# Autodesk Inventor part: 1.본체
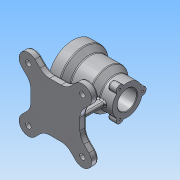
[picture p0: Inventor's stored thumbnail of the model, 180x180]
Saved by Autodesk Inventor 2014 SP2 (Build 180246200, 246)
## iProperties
Created: 2017-03
Part Number: 1.본체
Material: 알루미늄 6061
Document SubType Name: Modeling
Designer: SDA
Density: 2.71 g/cm^3
Appearance: 알루미늄 - 평지
Author: SDA
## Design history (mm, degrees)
sketch "스케치1"
  geometry: L1 (0, 0)-(100, 0); L2 (0, 0)-(0, 45); L3 (0, 45)-(20, 45); L4 (20, 45)-(31, 36); L5 (31, 36)-(65, 36); L6 (65, 36)-(77, 27.5); L7 (77, 27.5)-(100, 27.5); L8 (100, 27.5)-(100, 0)
  constraints: 16 end point, 4 horizontal, 2 vertical
  dimensions: "d0" = 100 distance of L1.start L1.end; "d1" = 90 diameter of L3 L1; "d2" = 72 diameter of L5 L1; "d3" = 55 diameter of L7 L1; "d4" = 20 distance of L2.end L3.end; "d5" = 31 distance from line of L4.end L2; "d6" = 65 distance from line of L2 L5.end; "d7" = 23 distance from line of L8 L6.end
revolve "회전1" sketch "스케치1" stored, may be unused: angle "d8" = 90 deg
sketch "스케치2"
  geometry: C1 r 35 at (0, 0); C2 r 45 at (0, 0) reference
  constraints: 1 centre point, 1 coincident
  dimensions: "d9" = 70 diameter of C1
extrude "돌출1" cut sketch "스케치2" distance "d10" = 23; taper "d11" = 0 deg
sketch "스케치4"
  geometry: C1 r 35 at (0, 0) reference; C2 r 26 at (0, 0)
  constraints: 1 centre point, 1 coincident
  dimensions: "d12" = 52 diameter of C2
extrude "돌출2" cut sketch "스케치4" distance "d13" = 47; taper "d14" = 0 deg
sketch "스케치5"
  geometry: C1 r 26 at (0, 0) reference; C2 r 17.5 at (0, 0)
  constraints: 1 centre point, 1 coincident
  dimensions: "d15" = 35 diameter of C2
extrude "돌출3" cut sketch "스케치5" distance "d16" = 30; taper "d17" = 0 deg
sketch "스케치6"
  geometry: C1 r 17.5 at (0, 0) reference; A1 r 7 centre (0, 27.5) between (6.943, 26.609) and (-6.943, 26.609); A2 r 27.5 centre (0, 0) between (-6.943, 26.609) and (6.943, 26.609) reference; A3 r 27.5 centre (0, 0) between (6.943, 26.609) and (-6.943, 26.609); A4 r 7 centre (-23.816, -13.75) between (-26.516, -7.292) and (-19.573, -19.317); A5 r 27.5 centre (0, 0) between (-26.516, -7.292) and (-19.573, -19.317); A6 r 7 centre (23.816, -13.75) between (19.573, -19.317) and (26.516, -7.292); A7 r 27.5 centre (0, 0) between (19.573, -19.317) and (26.516, -7.292); 1 further point
  constraints: 14 point on circle, 6 centre point, 1 coincident, 1 vertical alignment, 19 other
  dimensions: "d18" = 14 diameter of A1; "d19" = 27.5 distance of point (0, 0) A1.centre; "d23" = 360 deg dimension on A2.centre A1.centre (derived)
extrude "돌출4" join sketch "스케치6" distance "d25" = 15; taper "d26" = 0 deg
sketch "스케치7"
  geometry: A1 r 7 centre (0, 0) between (6.943, -0.891) and (-6.943, -0.891) reference; 1 further point
  constraints: 1 coincident
hole "구멍1" sketch "스케치7" at (0, 0) diameter "d27" = 3.459; stored, may be unused: countersink angle "d31" = 90 deg, drill point angle "d33" = 118 deg; dims "d28" = 9, "d29" = 4, "d30" = 2, "d32" = 11
sketch "스케치8"
  geometry: C1 r 35 at (0, 0) reference; 1 further point
  constraints: 1 vertical alignment
  dimensions: "d38" = 40 distance of C1.centre point (0, 40)
hole "구멍2" sketch "스케치8" at (0, 40) diameter "d39" = 3.459; stored, may be unused: countersink angle "d43" = 90 deg, drill point angle "d45" = 118 deg; dims "d40" = 9, "d41" = 4, "d42" = 2, "d44" = 11
node "작업 평면1"
sketch "스케치9"
  geometry: L1 (-11, 1.73)-(-12.039, 0) reference; L2 (-12.039, 0)-(-11, -1.73) reference; L3 (-11, -1.73)-(0, -1.73) reference; L4 (0, -1.73)-(0, -20.616) reference; L5 (0, -20.616)-(-20, -20.616) reference; L6 (-20, 20.616)-(0, 20.616) reference; L7 (0, 20.616)-(0, 1.73) reference; L8 (0, 1.73)-(-11, 1.73) reference; L9 (-31, 36)-(-65, 36) reference; L10 (-31, -36)-(-65, -36) reference; L11 (-100, 27.5)-(-100, 6.943) reference; C1 r 5 at (-50, 0); 2 further points
  constraints: 1 centre point, 1 vertical alignment
  dimensions: "d50" = 10 diameter of C1; "d51" = 36 distance from line of L9 C1.centre; "d52" = 50 distance from line of C1.centre L11
extrude "돌출5" join sketch "스케치9" stored distance "d53" = 15; taper "d54" = 0 deg
hole "구멍3" diameter "d57" = 4.459; stored, may be unused: countersink angle "d61" = 90 deg, drill point angle "d63" = 118 deg; dims "d58" = 14, "d59" = 4, "d60" = 2, "d62" = 14, "d174" = 10, "d175" = 10
node "작업 평면2"
sketch "스케치11"
  geometry: L1 (-10.072, 0)-(98.226, 0); L2 (11.518, 37.477)-(2.322, 28.281); L3 (-12.523, 61.518)-(-21.719, 52.322); L4 (-5, 0)-(-5, 10.603); L5 (-87.477, 61.518)-(-78.281, 52.322); L6 (-111.518, 37.477)-(-102.322, 28.281); L7 (-95, 0)-(-95, 10.603); L8 (-50, 45)-(-39.397, 45); L9 (-50, 45)-(-60.603, 45); L10 (11.518, -37.477)-(2.322, -28.281); L11 (-12.523, -61.518)-(-21.719, -52.322); L12 (-50, -45)-(-39.397, -45); L13 (-50, -45)-(-60.603, -45); L14 (-87.477, -61.518)-(-78.281, -52.322); L15 (-111.518, -37.477)-(-102.322, -28.281); L16 (-95, 0)-(-95, -10.603); L17 (-5, 0)-(-5, -10.603); C1 r 5 at (-50, 0) reference; C2 r 2.229 at (-50, 0) reference; A1 r 17 centre (-0.503, 49.497) between (11.518, 37.477) and (-13.894, 59.97); A2 r 25 centre (20, 10.603) between (2.322, 28.281) and (-5, 10.603); A3 r 17 centre (-99.497, 49.497) between (-87.477, 61.518) and (-111.518, 37.477); A4 r 25 centre (-120, 10.603) between (-95, 10.603) and (-102.322, 28.281); A5 r 25 centre (-39.397, 70) between (-39.397, 45) and (-21.719, 52.322); A6 r 25 centre (-60.603, 70) between (-78.281, 52.322) and (-60.603, 45); A7 r 25 centre (20, -10.603) between (-5, -10.603) and (2.322, -28.281); A8 r 17 centre (-0.503, -49.497) between (-12.523, -61.518) and (11.518, -37.477); A9 r 25 centre (-39.397, -70) between (-21.719, -52.322) and (-39.397, -45); A10 r 25 centre (-60.603, -70) between (-60.603, -45) and (-78.281, -52.322); A11 r 25 centre (-120, -10.603) between (-102.322, -28.281) and (-95, -10.603); A12 r 17 centre (-99.497, -49.497) between (-111.518, -37.477) and (-87.477, -61.518); 12 further points
  constraints: 34 end point, 25 point on circle, 12 centre point, 6 tangent, 2 horizontal, 1 parallel, 1 perpendicular, 1 vertical
extrude "돌출6" join sketch "스케치11" distance "d153" = 12; taper "d154" = 0 deg
sketch "스케치12"
  geometry: C1 r 5 at (0.503, 49.497); C2 r 5 at (99.497, 49.497); C3 r 5 at (99.497, -49.497); C4 r 5 at (0.503, -49.497); A1 r 17 centre (0.503, -49.497) between (-11.518, -37.477) and (12.523, -61.518) reference; A2 r 17 centre (99.497, -49.497) between (87.477, -61.518) and (111.518, -37.477) reference; A3 r 17 centre (99.497, 49.497) between (111.518, 37.477) and (87.477, 61.518) reference; A4 r 17 centre (0.503, 49.497) between (12.523, 61.518) and (-11.518, 37.477) reference; 1 further point
  constraints: 4 centre point, 4 coincident
  dimensions: "d155" = 10 diameter of C1; "d156" = 10 diameter of C2; "d157" = 10 diameter of C3; "d158" = 10 diameter of C4
extrude "돌출7" cut sketch "스케치12" distance "d159" = 12; taper "d160" = 0 deg
node "작업 평면3"
sketch "스케치13"
  geometry: L1 (45, -70)-(45, -82) reference; L2 (45, -82)-(-45, -82) reference; L3 (-45, -82)-(-45, -70) reference; L4 (-45, -70)-(45, -70) reference; L5 (5, 40)-(5, 35.651) reference; L6 (-5, 40)-(-2.229, 40) reference; L7 (-5, 35.651)-(-5, 40) reference; L8 (2.229, 40)-(5, 40) reference; L9 (37.477, -70)-(28.281, -70) reference; L10 (45, -70)-(52.322, -70) reference; L11 (0, -72)-(25, -72); L12 (25, -72)-(16.841, -25.731); L13 (16.841, -25.731)-(0, -31.644); L14 (-16.841, -25.731)-(0, -31.644); L15 (-25, -72)-(-16.841, -25.731); L16 (0, -72)-(-25, -72); L17 (-2.229, 40)-(-2.229, 26) reference; L18 (-2.229, 26)-(-2.09, 25.916) reference; L19 (2.09, 25.916)-(2.229, 26) reference; L20 (2.229, 26)-(2.229, 40) reference; A1 r 26 centre (0, 0) between (-2.09, 25.916) and (2.09, 25.916) reference; A2 r 36 centre (0, 0) between (-5, 35.651) and (5, 35.651) reference; 4 further points
  constraints: 12 end point, 2 point on line, 1 horizontal
  dimensions: "d165" = 100 deg angle of L12 L11; "d166" = 25 distance of L11.start L11.end; "d167" = 72 distance of point (0, 0) L11.start; "d197" = 25 horizontal distance of L15.start L13.end
extrude "돌출8" join sketch "스케치13" stored distance "d168" = 8; taper "d169" = 0 deg
sketch "스케치14"
  geometry: L1 (100, 17.5)-(70, 17.5) reference; L2 (70, 17.5)-(70, 26) reference; L3 (70, 26)-(52.23, 26) reference; L4 (52.23, 26)-(52.23, 40) reference; L5 (52.23, 40)-(55, 40) reference; L6 (55, 40)-(55, 36) reference; L7 (55, 36)-(65, 36) reference; L8 (65, 36)-(77, 27.5) reference; L9 (77, 27.5)-(85, 27.5) reference; L10 (85, 27.5)-(85, 34.5) reference; L11 (85, 34.5)-(100, 34.5) reference; L12 (100, 34.5)-(100, 29.23) reference; L13 (100, 29.23)-(89, 29.23) reference; L14 (89, 29.23)-(87.961, 27.5) reference; L15 (87.961, 27.5)-(89, 25.77) reference; L16 (89, 25.77)-(100, 25.77) reference; L17 (100, 25.77)-(100, 17.5) reference; L18 (23, 35)-(0, 35) reference; L19 (0, 35)-(0, 38.27) reference; L20 (0, 38.27)-(11, 38.27) reference; L21 (11, 38.27)-(12.039, 40) reference; L22 (12.039, 40)-(11, 41.73) reference; L23 (11, 41.73)-(0, 41.73) reference; L24 (0, 41.73)-(0, 45) reference; L25 (0, 45)-(20, 45) reference; L26 (20, 45)-(31, 36) reference; L27 (31, 36)-(45, 36) reference; L28 (45, 36)-(45, 40) reference; L29 (45, 40)-(47.77, 40) reference; L30 (47.77, 40)-(47.77, 26) reference; L31 (47.77, 26)-(23, 26) reference; L32 (23, 26)-(23, 35) reference; L33 (95, -70)-(95, -82) reference; L34 (95, -82)-(5, -82) reference; L35 (5, -82)-(5, -70) reference; L36 (5, -70)-(46, -70) reference; L37 (46, -70)-(46, -36) reference; L38 (46, -36)-(31, -36) reference; L39 (31, -36)-(20, -45) reference; L40 (20, -45)-(0, -45) reference; L41 (0, -45)-(0, -41.73) reference; L42 (0, -41.73)-(11, -41.73) reference; L43 (11, -41.73)-(12.039, -40) reference; L44 (12.039, -40)-(11, -38.27) reference; L45 (11, -38.27)-(0, -38.27) reference; L46 (0, -38.27)-(0, -35) reference; L47 (0, -35)-(23, -35) reference; L48 (23, -35)-(23, -26) reference; L49 (23, -26)-(70, -26) reference; L50 (70, -26)-(70, -17.5) reference; L51 (70, -17.5)-(100, -17.5) reference; L52 (100, -17.5)-(100, -27.5) reference; L53 (100, -27.5)-(77, -27.5) reference; L54 (77, -27.5)-(65, -36) reference; L55 (65, -36)-(54, -36) reference; L56 (54, -36)-(54, -70) reference; L57 (54, -70)-(95, -70) reference; L58 (50, -76.825)-(13, -76.825); L59 (13, -76.825)-(13, -40.425); L60 (13, -40.425)-(20.552, -38.461); L61 (20.552, -38.461)-(30.234, -30.539); L62 (30.234, -30.539)-(58.394, -30.539); L63 (58.394, -30.539)-(87, -23.561); L64 (87, -23.561)-(87, -76.825)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; 1 further point
  constraints: 16 end point, 3 horizontal, 2 vertical, 1 parallel
  dimensions: "d191" = 37 distance of L58.start L58.end; "d192" = 37 distance of L58.start L64.end
  node "절단 모서리 투영5"
chamfer "모따기1" distance "d176" = 1; stored, may be unused: second distance "d177" = 2, angle "d178" = 45 deg
fillet "모깎기1" dims "d179" = 3
fillet "모깎기2" dims "d180" = 3
fillet "모깎기3" dims "d181" = 3
fillet "모깎기4" dims "d182" = 1
sketch "스케치15"
  geometry: L1 (43, 21.072)-(43, -21.072) reference; L2 (49, -27.165)-(51, -27.165) reference; L3 (57, -21.072)-(57, 21.072) reference; L4 (51, 27.165)-(49, 27.165) reference; L5 (-9.397, 39.598)-(-0.201, 30.402) reference; L6 (8, 10.603)-(8, -10.603) reference; L7 (-0.201, -30.402)-(-9.397, -39.598) reference; L8 (10.402, -59.397)-(19.598, -50.201) reference; L9 (39.397, -42)-(60.603, -42) reference; L10 (80.402, -50.201)-(89.598, -59.397) reference; L11 (109.397, -39.598)-(100.201, -30.402) reference; L12 (92, -10.603)-(92, 10.603) reference; L13 (100.201, 30.402)-(109.397, 39.598) reference; L14 (89.598, 59.397)-(80.402, 50.201) reference; L15 (60.603, 42)-(39.397, 42) reference; L16 (19.598, 50.201)-(10.402, 59.397) reference; L17 (5, 10.603)-(5, -10.603) reference; L18 (95, -10.603)-(95, 10.603) reference; C1 r 5 at (99.497, -49.497) reference; C2 r 5 at (0.503, 49.497) reference; C3 r 5 at (99.497, 49.497) reference; C4 r 5 at (0.503, -49.497) reference; A1 r 14 centre (0.503, 49.497) between (10.402, 59.397) and (-9.397, 39.598) reference; A2 r 28 centre (-20, 10.603) between (8, 10.603) and (-0.201, 30.402) reference; A3 r 28 centre (-20, -10.603) between (-0.201, -30.402) and (8, -10.603) reference; A4 r 14 centre (0.503, -49.497) between (-9.397, -39.598) and (10.402, -59.397) reference; A5 r 28 centre (39.397, -70) between (39.397, -42) and (19.598, -50.201) reference; A6 r 28 centre (60.603, -70) between (80.402, -50.201) and (60.603, -42) reference; A7 r 14 centre (99.497, -49.497) between (89.598, -59.397) and (109.397, -39.598) reference; A8 r 28 centre (120, -10.603) between (92, -10.603) and (100.201, -30.402) reference; A9 r 28 centre (120, 10.603) between (100.201, 30.402) and (92, 10.603) reference; A10 r 14 centre (99.497, 49.497) between (109.397, 39.598) and (89.598, 59.397) reference; A11 r 28 centre (60.603, 70) between (60.603, 42) and (80.402, 50.201) reference; A12 r 28 centre (39.397, 70) between (19.598, 50.201) and (39.397, 42) reference; 2 further points
  constraints: 5 other
  dimensions: "d185" = 35 vertical distance of point (50, -35) point (0, 0); "d198" = 45 distance from line of L18 point (50, -35)
feature "엠보싱1" sketch "스케치15" dims "d0" = 100, "d1" = 90, "d2" = 72, "d3" = 55, "d4" = 20, "d5" = 31, "d6" = 65, "d7" = 23, "d12" = 52, "d186" = 0.5, "d187" = 0
extrude "돌출10" join sketch "스케치14" stored distance "d193" = 8; taper "d194" = 0 deg
fillet "모깎기5" dims "d195" = 3
fillet "모깎기6" dims "d196" = 3
node "솔리드1"
pattern_circular "원형 패턴1" dims angle "d35" = 360 deg
pattern_circular "원형 패턴2" dims angle "d47" = 360 deg
node "절단 모서리 투영1"
node "절단 모서리 투영2"
node "절단 모서리 투영4"
node "절단 모서리 투영6"
other parameters: "d64" = -82, "d75" = 51.47524
